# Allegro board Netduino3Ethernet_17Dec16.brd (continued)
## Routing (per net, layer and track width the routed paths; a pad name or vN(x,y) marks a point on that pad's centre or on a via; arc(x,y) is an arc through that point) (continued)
JTMS: length 24.6
  TOP w0.15: U4.72 46.28,28.77 46.27,28.78 46.27,30.1 46,30.38 v1(46,30.9) ; v1(58.25,31.7) 58.25,34.05 v1(55.2,37.1)
  BOTTOM w0.15: v1(55.2,37.1) 53.45,35.35 53.45,34.67 52.13,33.35 48.44,33.35 46.37,31.28 46.37,31.27 v1(46,30.9) ; J8.2 56.55,30.98 56.9,31.33 57.88,31.33 v1(58.25,31.7)
LED: length 16.5
  TOP w0.15: Q1.2 36.23,25.09 37.79,23.52 40.3,23.52 40.43,23.65 41.13,23.65 41.24,23.54 R8.4 41.46,23.11 v1(41.95,23.6)
  TOP w0.18: U4.69 47.78,27.07 48.07,26.78 v1(48.25,26.78)
  L2-GND w0.15: v1(41.95,23.6) 42.87,23.6 43.87,24.6 45.24,24.6 47.42,26.78 v1(48.25,26.78)
LED_GOPORT1: length 10.6
  TOP w0.15: U4.40 v1(57.38,21.08) ; v1(60.26,16.97) 60.65,16.97 60.7,16.93 60.94,16.93 61.42,16.45 63.52,16.45 63.75,16.68 Q10.2
  BOTTOM w0.15: v1(57.38,21.08) 59.3,19.16 59.3,18.8 60.26,17.84 v1(60.26,16.97)
LED_GOPORT2: length 8.7
  TOP w0.15: Q11.5 63.75,23.5 63.45,23.8 63,23.8 61.95,24.85 60.09,24.85 59.66,24.42 59.66,22.36 59.38,22.08 U4.42
LED_GOPORT3: length 9.2
  TOP w0.15: Q11.2 63.75,20.88 63.39,20.52 62.62,20.52 62.43,20.71 v1(61.9,20.71)
  TOP w0.18: U4.45 v1(57.37,23.58)
  BOTTOM w0.15: v1(61.9,20.71) 61.4,21.21 61.4,21.31 60.16,22.55 58.4,22.55 v1(57.37,23.58)
OSC_IN: length 7.5
  TOP w0.2: Y1.2 50.28,8.58 50.5,8.8 50.5,9.75 50.28,9.97 U4.12
  TOP w0.3: Y1.2 48.25,8.45 C18.1
OSC_OUT: length 1.3
  TOP w0.2: U4.13 50.78,11.27 R7.2
OTG_FS_DM: length 1.4
  TOP w0.18: R9.4 47.33,28.68 47.28,28.63 U4.70
OTG_FS_DP: length 1.5
  TOP w0.18: R9.3 46.67,28.68 46.78,28.57 U4.71
PWR_LED: length 19.5
  TOP w0.15: v1(48.15,13.8) 47.78,13.43 U4.7 ; R8.3 41.39,22.46 41.55,22.3 v1(41.55,21.75)
  TOP w0.18: Q1.5 v1(38.89,25.09)
  L2-GND w0.15: v1(41.55,21.75) 43.1,20.2 43.1,18.85 v1(48.15,13.8)
  BOTTOM w0.15: v1(41.55,21.75) 40.7,22.6 40.7,24.24 40.65,24.29 40.65,24.4 39.96,25.09 v1(38.89,25.09)
PWR_ON_GOPORT1: length 26.3
  TOP w0.15: Q6.5 63.75,14.52 62.4,13.17 62.4,13.13 61.34,12.07 60.15,12.07 59.17,13.05 58.25,13.05 55.85,15.45 55.65,15.45 54.31,16.78 53.57,16.78 50.9,19.45 50.9,19.76 50.61,20.06 50.32,20.06 49.53,20.85 45.67,20.85 44.9,20.08 U4.88
PWR_ON_GOPORT2: length 22.1
  TOP w0.15: v1(54.58,23.71) 54.58,24.7 54,25.28 54,26.42 53.98,26.85 53.78,27.05 U4.57
  TOP w0.18: Q6.2 v1(63.75,12.25)
  BOTTOM w0.15: v1(54.58,23.71) 56.7,21.58 58.86,21.58 60.17,20.27 60.17,19.55 62.17,17.55 62.66,17.55 63.02,17.19 63.02,15.52 63.75,14.79 v1(63.75,12.25)
PWR_ON_GOPORT3: length 19.4
  TOP w0.15: Q10.5 v1(63.75,18.2) ; U4.59 52.78,26.82 53.27,26.34 53.27,25.92 52.95,25.6 v1(52.95,24.2)
  BOTTOM w0.15: v1(52.95,24.2) 52.95,24.33 53.53,24.91 54.08,24.91 57.11,21.88 59.98,21.88 60.8,21.06 60.8,20.8 61.1,20.5 61.1,20.38 61.45,20.03 61.45,19.12 62.37,18.2 v1(63.75,18.2)
RD+: length 22.5
  TOP w0.18: D8.3 29.55,42.2 29.21,41.86 29.21,41.45 29.25,41.41 29.25,38.55 28.5,37.8 28.5,36.55 ; 28.5,36.55 T1.11 ; 28.5,36.55 28.76,36.28 31.72,36.28 32.08,36.65 U5.3
  TOP w0.3: T1.11 25.89,36.55 22.8,33.45 22.8,30.29 22.93,30.15 23.68,30.15
RD-: length 23
  TOP w0.18: D8.4 31.6,42.2 32.09,41.71 32.09,41.08 31.89,40.87 31.89,39.84 32.72,39.01 32.72,38.59 32.57,38.44 v1(32.57,38.14) ; v1(34.65,36.5) 34.4,36.25 U5.4 32.15,36.25 31.85,35.95 28.6,35.95 28.43,35.79 28.43,34.19 28.2,33.95 27.32,33.95 T1.9
  TOP w0.3: T1.9 25.5,34.01 23.68,32.17 23.68,31.05
  BOTTOM w0.18: v1(34.65,36.5) 34.21,36.5 v1(32.57,38.14)
RSET_BG: length 1.4
  TOP w0.2: U5.64 34.7,40 R21.1
RX+: length 9.8
  TOP w0.3: T1.6 17.57,36.55 16.75,37.37 16.75,40.35 15.69,41.41 J13.3
RX-: length 5.7
  TOP w0.3: J13.6 16.95,35.92 16.95,34.68 17.62,34.01 T1.8
SCL: length 57.7
  TOP w0.15: v1(41.15,18.73) 41.79,18.08 U4.92
  BOTTOM w0.15: v1(41.15,18.73) 41.58,18.3 43.63,18.3 45.5,20.17 45.5,20.26 46.5,21.26 46.5,22.81 46.11,23.2 43.81,25.5 42.13,25.5 42.08,25.55 41.95,25.55 39.05,28.45 39.05,29.11 37.68,30.48 37.17,30.48 36.7,30.94 36.7,31.82 36.8,31.92 36.8,35.22 37.8,36.22 37.8,37.61 36.15,39.26 36.15,42.81 31.86,47.1 22.5,47.1 J3.10
SDA: length 57.4
  TOP w0.15: U4.93 41.57,17.58 v1(41.15,18)
  BOTTOM w0.15: J3.9 21.34,49.41 23.2,47.55 31.95,47.55 38.1,41.4 38.1,37.32 38.1,37.32 38.1,36.1 37.1,35.1 37.1,31.79 37,31.69 37,31.07 37.29,30.77 37.81,30.77 39.35,29.23 39.35,28.72 42.17,25.9 43.84,25.9 46.24,23.5 46.8,22.94 46.8,19.72 45.08,18 v1(41.15,18)
SPI3_MISO: length 59.7
  TOP w0.15: U4.79 42.32,24.58 42.15,24.75 v1(41.75,24.75)
  TOP w0.18: v1(29.07,11.62) 26.21,11.62 22.13,15.7 16.57,15.7 15.59,16.68 15.35,16.68 14.75,17.29 J9.7 ; R5.4 43.4,8.62 v1(42.93,8.15)
  L2-GND w0.15: v1(41.75,24.75) 40.3,23.3 38.82,23.3 38.2,22.68 38.2,22 38.5,21.7 38.64,21.7 38.94,21.41 38.94,21.26 40.25,19.95 40.25,17.72 40.6,17.37 41.93,17.37 42.4,16.91 42.4,16.9 42.4,14.68 40.4,12.68 40.4,11.09 40.69,10.8 41.93,10.8 43.08,9.66 43.08,9.24 42.93,9.1 v1(42.93,8.15)
  BOTTOM w0.15: v1(29.07,11.62) 30.45,10.25 38,10.25 40.1,8.15 v1(42.93,8.15)
SPI3_MOSI: length 28.8
  TOP w0.15: v1(39.87,24.02) 40.46,24.02 40.54,24.1 42.16,24.1 42.18,24.08 U4.80
  TOP w0.18: v1(18.76,17.02) 19.15,17.41 J9.3
  BOTTOM w0.15: v1(39.87,24.02) 39.56,23.71 38.81,23.71 36.35,21.25 31.65,21.25 29.95,19.55 28.75,19.55 27.15,17.95 26.96,17.95 26.91,17.9 25.08,17.9 24.73,18.25 19.93,18.25 18.76,17.08 v1(18.76,17.02)
SPI3_SCK: length 34.9
  TOP w0.15: U4.78 42.13,25.08 41.96,25.25 40.23,25.25 39.21,24.23 v1(39.18,24.23)
  TOP w0.18: J9.5 16.95,17.1 17.8,16.25 v1(19.07,16.25)
  BOTTOM w0.15: v1(19.07,16.25) 19.26,16.44 19.26,17.16 20.05,17.95 24.61,17.95 24.96,17.6 27.03,17.6 27.08,17.65 27.55,17.65 29.11,19.21 30.04,19.21 31.77,20.95 36.55,20.95 38.96,23.36 39.92,23.36 40.37,23.81 40.37,24.15 40.35,24.17 40.35,24.25 40,24.6 39.55,24.6 v1(39.18,24.23)
SPI4_MISO: length 61.7
  TOP w0.15: 74.3,25.4 74.3,23.16 74.9,22.56 74.9,21.49 74.21,20.8 72.7,20.8 ; 74.3,25.4 73.8,25.9 73.8,30.73 73.29,31.23 73.29,32.27 76.55,35.52 76.55,36.9 74.25,39.2 74.25,41.7 74.5,41.95 75.92,41.95 J12.8 ; 74.3,25.4 J11.8 ; 72.7,20.8 71.5,22 71.5,22.16 69.96,23.7 64.2,23.7 63.8,24.1 63.12,24.1 62.07,25.15 59.97,25.15 59.36,24.54 59.36,23.24 59.2,23.08 U4.44 ; 72.7,20.8 72.53,20.63 72.53,16.32 74.07,14.78 74.07,14.22 74.05,14.2 74.05,11.66 74.35,11.36 74.35,10.58 73.78,10.01 73.78,9.38 74.33,8.82 J10.8
SPI4_MOSI: length 74.2
  TOP w0.15: J12.7 69.33,41.98 68.65,41.3 68.65,32.45 v1(70.25,30.85) ; 69.75,9.3 70.23,8.82 J10.7 ; 69.75,9.3 69.75,16.17 71.75,18.17 71.75,18.61 71,19.36 v1(71,21.95) ; 69.75,9.3 69,9.3 66.91,11.39 59.9,11.39 58.9,12.39 58.11,12.39 58.08,12.42 58.06,12.42 58.03,12.45 58,12.45 55.63,14.82 55.35,14.82 54.01,16.16 52.27,16.16 50.13,18.3 49.22,18.3 47.92,17 47.92,14.78 46.78,13.63 U4.5
  TOP w0.18: v1(70.39,24.59) 70.39,25.03 70.76,25.4 J11.7
  BOTTOM w0.15: v1(70.25,30.85) 70.25,27.65 70.9,27 70.9,25.1 v1(70.39,24.59)
  BOTTOM w0.18: v1(70.39,24.59) 71,23.99 v1(71,21.95)
SPI4_SCK: length 76.7
  TOP w0.15: U4.1 44.78,15.09 48.29,18.6 50.3,18.6 52.41,16.48 54.15,16.48 55.51,15.12 55.76,15.12 58.13,12.75 58.15,12.75 58.18,12.72 59.04,12.72 60.04,11.72 67.98,11.72 v1(69,10.7) ; J11.9 72.07,24.11 73.57,24.11 ; J12.9 72.05,40.06 69.7,37.72 69.7,34.4 73.5,30.6 73.5,25.78 73.57,25.7 73.57,24.11 ; 73.57,24.11 73.57,23.18 v1(74.4,22.35) ; v1(73.57,14.55) 73.57,11.43 v1(73.85,11.15) 73.85,10.51 73.47,10.13 73.47,9.25 73.65,9.08 73.65,7.7 73.5,7.55 J10.9
  BOTTOM w0.15: v1(73.85,11.15) 70.9,11.15 70.45,10.7 v1(69,10.7)
  BOTTOM w0.18: v1(74.4,22.35) 74.4,21.81 74.56,21.64 74.56,15.54 v1(73.57,14.55)
SWITCH1: length 103.1
  TOP w0.15: v1(59.62,17.32) 60.15,17.84 R12.1 ; SW1.4 12.2,47.78 13.13,46.85 21.82,46.85 22.95,45.73 v1(22.95,45.2) ; v1(41.87,18.8) 42.09,18.58 U4.91 43.8,18.58 43.95,18.43 43.95,17.23 43.8,17.08 U4.94 ; U4.58 53.28,27.13 53.57,26.84 53.57,25.28 53.74,25.11 v1(53.74,24.41)
  L2-GND w0.15: v1(41.87,18.8) 42.24,19.17 42.24,20.35 41.05,21.54 41.05,21.96 41.34,22.25 41.76,22.25 45.06,18.95 51.35,18.95 52.1,18.2 55.25,18.2 55.47,17.98 56.13,17.98 56.74,18.59 58.35,18.59 v1(59.62,17.32)
  BOTTOM w0.15: v1(59.62,17.32) 57.86,19.07 57.86,19.71 53.74,23.84 v1(53.74,24.41) ; v1(22.95,45.2) 23.48,45.2 23.62,45.35 28.75,45.35 29.35,44.75 29.35,44.55 30.12,43.78 31.83,43.78 32.25,43.36 32.25,42.94 31.07,41.77 31.07,41.61 31.04,41.57 31.04,41.16 31.07,41.12 31.07,40.1 31.82,39.35 32.5,39.35 34.25,37.61 34.25,37.29 34.54,37 34.86,37 35.85,36.01 35.85,35.99 36.14,35.7 36.16,35.7 36.5,35.36 36.5,32.04 36.4,31.94 36.4,31.07 36.4,30.82 37.04,30.18 37.56,30.18 38.75,28.98 38.75,28.28 41.78,25.25 41.96,25.25 42.11,25.1 43.79,25.1 46.2,22.69 46.2,21.38 45.2,20.38 45.2,20.29 43.71,18.8 v1(41.87,18.8)
TD+: length 31.6
  TOP w0.18: T1.16 28.25,42.9 28.5,42.65 v1(28.85,42.65) 28.85,42.95 29.1,43.2 D8.1 ; U5.6 32.5,35.45 32.35,35.6 v1(32.23,35.6)
  TOP w0.3: T1.16 25.95,42.9 21.75,38.7 21.75,29.48 22.77,28.45 23.68,28.45
  BOTTOM w0.15: v1(32.23,35.6) 32.23,37.78 31.68,38.33 31.38,38.33 31.05,38.66 31.05,38.71 29.23,40.53 29.23,42.27 v1(28.85,42.65)
TD-: length 32.4
  TOP w0.18: v1(31.75,43.15) 31.7,43.2 D8.6 ; v1(31.88,34.97) 32.42,34.97 32.51,35.05 U5.7 ; T1.14 28.31,40.35 v1(28.72,40.76)
  TOP w0.3: T1.14 26.11,40.35 22.2,36.45 22.2,29.93 22.77,29.35 23.68,29.35
  BOTTOM w0.15: v1(31.88,34.97) 31.73,35.12 31.73,35.83 31.85,35.95 31.85,37.73 31.56,38.02 31.26,38.02 30.75,38.53 30.43,38.53 28.93,40.03 28.93,40.55 v1(28.72,40.76)
  BOTTOM w0.18: v1(28.72,40.76) 28.34,41.15 28.34,42.86 28.69,43.21 30.09,43.21 30.09,43.22 30.51,43.22 30.51,43.21 31.15,43.21 31.21,43.15 v1(31.75,43.15)
TX+: length 6.4
  TOP w0.3: J13.1 16.05,43.95 17.11,42.9 T1.1
TX-: length 4.4
  TOP w0.3: J13.2 17.59,40.35 T1.3
USART3_RX_GOPORT1: length 30.6
  TOP w0.15: v1(70.35,9.4) 70.35,9.93 70.52,10.09 J10.5 ; v1(55.4,24.3) 54.3,25.4 54.3,26.96 54.28,26.98 U4.56
  BOTTOM w0.15: v1(70.35,9.4) 69.66,10.1 68.89,10.1 68.5,10.49 68.5,10.75 65.53,13.72 65.45,13.72 64.53,14.65 64.53,14.87 63.9,15.49 63.9,17.1 64.25,17.45 64.25,18.41 63.96,18.7 62.29,18.7 61.77,19.22 61.77,20.13 61.4,20.5 61.4,20.63 61.1,20.93 61.1,21.18 60.1,22.18 57.52,22.18 v1(55.4,24.3)
USART3_TX_GOPORT1: length 44.1
  TOP w0.15: U4.55 54.78,28.98 v1(54.85,29.05) ; v1(54.2,30.85) 53.83,31.22 53.83,31.27 53.65,31.45 R1.7 ; v1(74.05,21.35) 72.93,21.35 67.85,26.43 67.85,30.75 66.05,32.55 v1(64.2,32.55) ; J10.4 75.67,11.64 74.49,11.64 74.35,11.78 74.35,14.05 74.37,14.07 74.37,15.53 73.9,16 v1(73.9,17.8)
  L2-GND w0.15: v1(64.2,32.55) 61.75,32.55 58.95,29.75 57.7,29.75 57,29.05 v1(54.85,29.05)
  BOTTOM w0.15: v1(73.9,17.8) 73.9,21.2 v1(74.05,21.35) ; v1(54.85,29.05) 54.85,30.2 v1(54.2,30.85)
USART7_RX_GOPORT2: length 23.7
  TOP w0.15: J11.5 70.59,26.67 70.25,26.32 v1(70.25,25.61) ; U4.38 v1(55.07,20.08)
  L2-GND w0.15: v1(55.07,20.08) 58.04,23.05 64.31,23.05 64.88,23.62 65.53,23.62 65.63,23.53 68.23,23.53 69.4,24.7 69.4,24.76 v1(70.25,25.61)
USART7_TX_GOPORT2: length 52.5
  TOP w0.15: U4.39 54.09,20.58 54.06,20.55 53.64,20.55 53.35,20.84 53.35,20.97 51.91,22.42 51.91,23.89 50.59,25.21 49.72,25.21 49.43,25.5 49.43,25.92 49.72,26.21 50.65,26.21 51.26,25.6 v1(52,25.6) ; R1.6 53.6,30.95 53.7,30.85 53.7,30.64 53.88,30.46 53.88,30.04 v1(53.92,30.01) ; v1(73.79,31.89) 73.79,31.16 74.2,30.75 74.2,28.24 74.5,27.94 J11.4 ; v1(58.93,32.32) 59.57,32.32 60.6,33.35 66.55,33.35 69.55,30.35 70.53,30.35 71.05,30.87 71.05,31.39 v1(71.53,31.87)
  BOTTOM w0.15: v1(58.93,32.32) 57.47,32.32 56.35,31.2 54.97,31.2 54.82,31.35 53.99,31.35 53.7,31.06 53.7,30.22 v1(53.92,30.01) 53.92,27.98 52.27,26.34 52.27,25.84 52.03,25.6 v1(52,25.6) ; v1(71.53,31.87) 72.05,31.87 72.08,31.89 v1(73.79,31.89)
USART8_RX_GOPORT3: length 45.6
  TOP w0.15: v1(49.15,20.05) 48.5,20.05 44.03,15.58 U4.97 ; v1(67.5,43.45) 70.4,43.45 70.6,43.25 J12.5
  BOTTOM w0.15: v1(67.5,43.45) 62.75,38.7 59.45,38.7 59.27,38.52 54.98,34.23 54.98,33.24 52.76,31.02 52.76,29.96 52.74,29.95 52.74,29.53 52.76,29.51 52.76,27.68 51.67,26.58 51.67,26.53 51.03,25.9 51.03,25.5 51.03,25.26 49.15,23.37 v1(49.15,20.05)
USART8_TX_GOPORT3: length 57.2
  TOP w0.15: v1(73.6,47.85) 74.25,47.2 74.25,44.77 74.5,44.52 J12.4 ; U4.98 44.32,15.08 48.77,19.52 v1(49.67,19.52) ; v1(53.24,29.74) 53.24,30.26 R1.5
  BOTTOM w0.15: v1(49.67,19.52) 49.67,20.23 49.55,20.36 49.55,23.35 51.33,25.13 51.33,25.77 51.97,26.41 51.97,26.46 53.24,27.74 v1(53.24,29.74) 53.24,31.07 55.28,33.11 55.28,34.11 59.47,38.3 63.06,38.3 69.7,44.94 69.7,47.15 71.1,48.55 72.9,48.55 v1(73.6,47.85)
USB5V: length 4.3
  TOP w0.3: 7.05,23.52 7.05,24.65 F1.1
  TOP w0.4: J5.1 5.87,24.12 6.55,24.8 F1.1
USB5V_F: length 65
  TOP w0.15: Q3.3 5,30.62 5.7,31.32 6.7,31.32 7.12,31.75 8.9,31.75 9.12,31.52 9.12,29.62 9.6,29.15 10.55,29.15 10.75,28.95 11.52,28.95 12.18,28.3 12.18,28.29 13.31,27.15 19.11,27.15 19.22,27.04 27.39,27.04 28.2,27.85 35.74,27.85 36.44,28.55 36.86,28.55 37.06,28.35 37.3,28.35 37.48,28.17 40,28.17 41.12,29.3 41.12,32.42 v1(40.27,33.27)
  TOP w0.18: U4.68 v1(48.28,28.97)
  TOP w0.8: Q3.3 5.85,28.85 F1.2
  BOTTOM w0.15: v1(48.28,28.97) 47.12,28.97 42.2,33.89 42.2,34.64 41.11,35.73 40.33,35.73 39.3,34.71 39.3,34.25 v1(40.27,33.27)
USB_D+: length 49.1
  TOP w0.18: 6.55,22.7 5.24,22.7 5.12,22.82 J5.3 ; 6.55,22.7 D4.1 ; 6.55,22.7 8.3,22.7 8.5,22.5 8.5,22.15 8.6,22.05 8.85,22.05 8.98,22.18 8.98,22.57 9.1,22.7 9.5,22.7 10.45,23.65 10.45,24.21 12.25,26 12.72,26.47 18.88,26.47 18.95,26.39 27.69,26.39 28.49,27.19 40.39,27.19 42.2,29 42.2,29.48 44.13,31.42 46.35,31.42 46.67,31.09 R9.2
USB_D-: length 49
  TOP w0.18: 6.55,23.04 5.55,23.04 5.12,23.47 J5.2 ; 6.55,23.04 9.34,23.04 10.12,23.82 10.12,24.07 10.12,24.34 12.11,26.34 12.11,26.34 12.41,26.64 12.58,26.8 19.01,26.8 19.09,26.72 27.56,26.72 28.35,27.52 40.25,27.52 41.87,29.14 41.87,29.62 43.76,31.51 43.99,31.75 46.67,31.75 47.33,31.09 R9.1 ; 6.55,23.04 6.55,23.52
VCAP_1: length 2.5
  TOP w0.25: C17.1 59.94,25.7 59.82,25.58 U4.49
VCAP_2: length 2.1
  TOP w0.3: C16.1 45.5,29.15 45.78,28.87 U4.73
XTALIN: length 8.5
  TOP w0.2: U5.61 35.9,39.45 36.32,39.87 36.32,40.32 R16.1 36.5,40.55 36.35,40.7 36.35,41.35 36.6,41.6 36.6,42.7 37.3,43.4 Y2.2 39.25,44.1 C37.1
XTALOUT: length 8.6
  TOP w0.2: U5.62 35.5,39.6 35.75,39.85 35.75,40.35 R16.2 35.6,40.55 35.75,40.7 35.75,41.25 36.25,41.75 36.25,42.7 35.55,43.4 Y2.1 33.55,44.1 C38.1
N332853: length 10.3
  TOP w0.15: R5.8 44.4,10.8 44.05,11.15 44.05,11.35 43.2,12.2 41.91,12.2 41.85,12.14 39.06,12.14 38.52,11.61 38.52,11.19 38.97,10.75 39,10.75 ; Q2.3 39.15,10.1 39,10.25 39,10.75 ; 39,10.75 Q2.2
N332873: length 2.9
  TOP w0.6: L1.1 38.33,15.65 U1.5
N332891: length 23.4
  TOP w0.15: R1.1 51.9,33.19 50.95,34.14 50.95,35.02 51.85,35.92 51.85,36.58 51.45,36.98 v1(51.45,41.65) ; D2.C 61.76,42.61 59.65,40.5 55.55,40.5 v1(54.65,41.4)
  BOTTOM w0.15: v1(54.65,41.4) 53.15,41.4 52.9,41.65 v1(51.45,41.65)
N333149: length 24.5
  TOP w0.15: v1(36.65,28.05) 37.17,28.05 37.35,27.87 40.12,27.87 41.55,29.3 41.55,29.85 v1(44.25,32.55) ; Q1.6 37.69,26.19 37.58,26.3 v1(36.8,26.3) ; v1(52.1,34.35) 52.1,33.7 53.1,32.7 R1.8
  BOTTOM w0.15: v1(36.65,28.05) 36.65,27.25 36.8,27.1 v1(36.8,26.3) ; v1(44.25,32.55) 45.8,32.55 47,33.75 51.5,33.75 v1(52.1,34.35)
N333173: length 2.4
  TOP w0.2: R3.1 8.91,18.33 9.79,19.2 9.8,19.2 D1.C
N333175: length 35.9
  TOP w0.15: v1(24.4,17.45) 25.85,18.9 27.6,18.9 27.95,18.55 29.76,18.55 29.76,18.55 31.76,18.55 32.4,19.18 32.4,21.3 35,23.9 35.64,23.9 35.79,24.05 Q1.3 ; v1(11.55,17.98) 10.89,17.98 9.64,16.73 R3.2
  BOTTOM w0.15: v1(11.55,17.98) 11.92,18.35 13.25,18.35 14.45,17.15 14.45,15.59 14.74,15.3 18.83,15.3 19.57,16.05 19.57,16.36 19.56,16.37 19.56,17.03 20.03,17.5 20.69,17.5 20.74,17.45 v1(24.4,17.45)
N333299: length 6.1
  TOP w0.2: Y1.1 51.17,8.58 51,8.75 51,9.75 51.75,10.5 51.75,11 R7.1
  TOP w0.3: Y1.1 52.81,8.45 C19.1
N333445: length 12.9
  TOP w0.18: J9.1 21.35,17.29 26.57,12.06 28.56,12.06 29.15,12.65 29.15,13.59 28.99,13.75 R11.6
N333449: length 23.4
  TOP w0.18: R11.7 29.12,14.25 29.59,13.78 29.59,11.41 29.29,11.11 26.26,11.11 22,15.37 16.38,15.37 15.39,16.35 14.45,16.35 13.65,17.15 J9.8
N337920: length 7.7
  TOP w0.15: Q10.6 62.65,18.95 62.4,19.2 v1(62.4,19.3) ; v1(60.2,24.25) 60.15,24.2 R15.8
  BOTTOM w0.15: v1(60.2,24.25) 60.2,24.25 60.2,23.11 62.19,21.12 62.2,21.12 62.4,20.92 62.4,19.3 v1(62.4,19.3)
N337928: length 32.1
  TOP w0.15: v1(59.58,20.15) 59.58,20.91 60.15,21.48 R15.1
  TOP w0.18: v1(71.45,2.55) D5.C
  BOTTOM w0.15: v1(59.58,20.15) 59.67,20.06 59.67,19.03 61.25,17.45 61.25,16.7 61.4,16.55 61.4,11.59 60.95,11.14 60.95,4.9 61.5,4.35 62.35,4.35 62.85,3.85 64.15,3.85 66,2 70.9,2 v1(71.45,2.55)
N337930: length 6.3
  TOP w0.15: R15.7 60.7,23.3 60.7,24.13 v1(60.92,24.35) ; Q11.3 64.35,21.1 64.35,21.6 v1(63.85,22.1)
  BOTTOM w0.15: v1(63.85,22.1) 63.43,22.52 62.75,22.52 v1(60.92,24.35)
N337938: length 16.3
  TOP w0.15: v1(71.25,18.4) 70.45,19.2 69.1,19.2 67.93,20.38 64.97,20.38 64.82,20.52 63.82,20.52 63.5,20.21 61.65,20.21 60.7,21.16 R15.2 ; v1(73.1,17.85) 73.1,19.05 D6.C
  BOTTOM w0.15: v1(73.1,17.85) 72.55,18.4 v1(71.25,18.4)
N337940: length 3
  TOP w0.15: Q11.6 63.1,23.05 62.72,23.43 62.72,23.65 62.45,23.93 61.35,23.93 61.2,23.77 R15.6
N337948: length 24.3
  TOP w0.15: v1(62.4,21.62) 62.03,21.25 61.42,21.25 61.2,21.48 R15.3
  TOP w0.18: v1(70.2,35.4) 72.14,35.4 72.49,35.75 D7.C
  BOTTOM w0.15: v1(70.2,35.4) 67.45,32.65 67.45,24.85 66.45,23.85 65.12,23.85 64.35,23.08 64.35,21.89 63.76,21.3 62.72,21.3 v1(62.4,21.62)
N337960: length 36.7
  TOP w0.15: v1(29.25,16.93) 28.9,16.58 Q4.3 ; v1(50.5,32.65) 51.15,32 51.15,31.57 51.27,31.45 R1.2
  L2-GND w0.15: v1(29.25,16.93) 30.78,16.93 34.05,20.2 34.05,29.18 34.49,29.62 35.67,29.62 35.97,29.93 40.92,29.93 44.04,33.05 46.2,33.05 46.45,33.3 48.45,33.3 49.1,32.65 v1(50.5,32.65)
N337994: length 2.2
  TOP w0.15: Q8.6 50.7,31.8 50.85,31.65 50.85,31.38 51.27,30.95 R1.3
N338028: length 4.6
  TOP w0.15: Q8.3 48.78,30.5 49.93,29.35 50.4,29.35 50.69,29.64 50.69,29.81 51.27,30.4 R1.4
N338320: length 11.8
  TOP w0.18: R19.2 31.96,24.94 31.85,25.05 v1(31.7,25.05) ; U5.12 32.65,33.05 32.47,32.87 v1(32,32.87)
  BOTTOM w0.15: v1(31.7,25.05) 31.28,25.47 31.28,26.05 31.91,26.68 31.91,29.54 32.88,30.51 32.88,32.52 32.52,32.87 v1(32,32.87)
N338324: length 10
  TOP w0.18: v1(31.78,25.77) 32.07,25.49 R19.1 ; U5.13 v1(34.52,32.65)
  BOTTOM w0.15: v1(34.52,32.65) 33.53,31.66 33.53,30.74 32.25,29.46 32.25,26.24 v1(31.78,25.77)
N338328: length 25.8
  TOP w0.15: v1(32.4,23.1) 32.1,22.8 32.1,19.31 31.64,18.84 29.89,18.84 29.88,18.85 29.55,18.85 29.4,19 R13.2
  TOP w0.18: U5.57 37.5,37.99 37.96,37.53 37.96,34.21 v1(36,32.25)
  BOTTOM w0.15: v1(36,32.25) 35.54,31.79 34.91,31.79 34.6,31.48 34.6,29.85 33.55,28.8 33.55,26.39 32.4,25.24 v1(32.4,23.1)
N338332: length 10.3
  TOP w0.15: R19.6 34.85,24.44 35.14,24.73 35.14,25.14 34.85,25.44 34.84,25.44 33.77,26.5 v1(32.95,26.5)
  TOP w0.18: U5.16 33.45,30.8 v1(34,30.25)
  BOTTOM w0.15: v1(34,30.25) 33.55,29.8 33.55,29.34 32.95,28.74 v1(32.95,26.5)
N338402: length 16.9
  TOP w0.18: R14.5 38.14,21.5 v1(38.44,21.2) ; U5.21 v1(36.3,29.12)
  BOTTOM w0.15: v1(38.44,21.2) 39.24,22 40.59,22 41.34,21.25 41.76,21.25 42.05,21.54 42.05,22.55 41.04,23.56 41.04,24.33 40.95,24.42 40.95,24.75 37.15,28.55 36.88,28.55 v1(36.3,29.12)
N338408: length 14.2
  TOP w0.15: v1(31.35,23.55) 31.75,23.55 32.09,23.89 R19.4
  TOP w0.18: U5.20 v1(35.9,31.27)
  BOTTOM w0.15: v1(35.9,31.27) 35.9,30.75 35.8,30.65 35.8,29.4 33.9,27.5 33.9,26.3 32.9,25.3 32.9,22.89 32.61,22.6 32.19,22.6 31.9,22.89 31.9,23 v1(31.35,23.55)
N338436: length 3.6
  TOP w0.3: R17.6 27,29.35 C51.1 27.14,28.92 26.68,28.45 R17.5
N338444: length 3.8
  TOP w0.3: R17.8 26.75,31.05 27.14,30.65 C39.1 27.11,30.07 26.48,30.07 26.4,30.15 R17.7
N338526: length 11.6
  TOP w0.3: R18.4 12.46,33.8 11.54,34.72 11.54,37.67 J13.5 14,38.87 J13.4
N338532: length 8.5
  TOP w0.3: R18.3 13.35,33.85 12.73,34.47 J13.7 14,36.33 J13.8
N338540: length 17.3
  TOP w0.3: T1.2 20.02,41.62 20.85,40.8 20.85,33.3 20.1,32.55 15.35,32.55 15.04,32.25 R18.1
N338544: length 10.5
  TOP w0.3: T1.7 19.89,35.27 20.15,35.02 20.15,33.5 19.75,33.1 15.18,33.1 14.15,32.08 R18.2
N338558: length 8.2
  TOP w0.3: C40.1 15.2,28.1 15.04,28.25 ; 15.04,28.25 14.15,28.25 ; 15.04,28.25 R18.8 ; 14.15,28.25 R18.7 ; 14.15,28.25 13.35,28.25 ; 13.35,28.25 R18.6 ; 13.35,28.25 12.79,28.25 12.55,28.5 12.55,29.13 R18.5
N3392501: length 18.5
  TOP w0.18: R22.4 12.59,45.67 12.42,45.51 8.95,45.51 6.8,47.65 2.98,47.65 2.4,48.23 D9.1
N3395001: length 17.9
  TOP w0.18: R22.3 12.77,46.33 12.28,45.84 10.7,45.84 6.71,49.82 4.54,49.82 3.77,49.05 D9.2

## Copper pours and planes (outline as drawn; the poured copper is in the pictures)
+3.3V on TOP: 35.1,14 35.1,11.25 37.7,11.25 38,11.55 38,11.85 39,12.85 40.05,12.85 40.05,13.9 36.6,13.9 36.5,14
+3.3V on L3-PWR: outline of 91 points within 9.5,8.5 67.5,48.25
+5.0V on TOP: 29.85,17.75 29.85,15.4 30.2,15.4 30.2,14.6 31.75,14.6 31.75,15.4 33.5,15.4 33.5,17.75
+5.0V on TOP: 3.45,27.5 1.35,27.5 1.35,30.1 2.25,30.1 2.25,28.3 3.45,28.3
+5.0V on TOP: 17.95,26.2 17.95,19.2 28.1,19.2 28.1,21.2 30.8,21.2 30.8,22.9 28.1,22.9 28.1,26.2
+5.0V on BOTTOM: 0.5,0.5 0.5,35.75 8.75,35.75 9.81,36.19 10.25,37.25 10.25,41.75 9.81,42.81 8.75,43.25 0.5,43.25 0.5,52.75 15.25,52.75 15.25,50.75 18.75,50.75 22.5,47 23.5,47 23.5,45.25 28.75,45.25 28.75,38.25 28.25,37.75 28.25,34.25 28.75,33.75 28.75,32 28.25,31.5 28.25,26 28.75,25.5 28.75,0.5 ; 2 cut-outs
+5.0V on L2-GND: 17.75,19.25 17.75,26.5 28.25,26.5 28.25,19.25
+5.0V on L3-PWR: 0.5,52.75 0.5,43.25 8.75,43.25 9.81,42.81 10.25,41.75 10.25,37.25 9.81,36.19 8.75,35.75 0.5,35.75 0.5,0.5 76.25,0.5 77.5,1.75 77.5,51.5 76.25,52.75
GND on TOP: 0.5,0.5 0.5,35.75 8.75,35.75 9.81,36.19 10.25,37.25 10.25,41.75 9.81,42.81 8.75,43.25 0.5,43.25 0.5,52.75 76.25,52.75 77.5,51.5 77.5,1.75 76.25,0.5 ; 68 cut-outs
GND on TOP: 33.8,15.75 34.8,15.75 34.8,13.4 34.25,12.85 34.25,11.45 30.25,11.45 30.25,12.5 32.1,12.5 32.1,13.1 32.15,13.15 33.8,13.15 33.8,14.45 32.4,14.45 32.4,14.9 32.45,14.95 33.8,14.95
GND on TOP: 5.75,21.7 5.75,19.2 6.75,19.2 6.75,21.7
GND on BOTTOM: 0.5,52.75 0.5,43.25 8.75,43.25 9.81,42.81 10.25,41.75 10.25,37.25 9.81,36.19 8.75,35.75 0.5,35.75 0.5,0.5 76.25,0.5 77.5,1.75 77.5,51.5 76.25,52.75 ; 20 cut-outs
GND on L2-GND: 0.5,52.75 0.5,43.25 8.75,43.25 9.81,42.81 10.25,41.75 10.25,37.25 9.81,36.19 8.75,35.75 0.5,35.75 0.5,0.5 76.25,0.5 77.5,1.75 77.5,51.5 76.25,52.75 ; 11 cut-outs
VCC3A3 on L3-PWR: 32.25,46.5 32.5,46.25 32.5,45 31.75,44.25 31.75,43 32.75,42 32.75,39.75 31.5,39.75 30.75,39 30.75,37.25 28,37.25 26.25,35.5 26.25,35 25.75,35 25.5,35.25 25.5,45.25 26.75,46.5
VCC18 on L3-PWR: 43.75,34.25 43.75,34.75 43.5,35 43.25,35 41.5,36.75 41.5,39.5 40.25,40.75 39.63,40.75 38.13,39.25 37.25,39.25 37,39.5 31.5,39.5 31,39 31,37.25 31.5,37.25 31.75,37 31.75,36.5 31.5,36.25 30.75,36.25 28.75,34.25 28.75,33.25 30.25,33.25 30.5,33.5 30.5,33.75 31.5,34.75 32.5,34.75 35.75,38 36,38 36.5,37.5 36.5,36.25 35.25,35 35.25,34.75 37.25,32.75 37.25,30 39.5,30
VCC18A on L3-PWR: 31.5,34.5 30.75,33.75 30.75,33.5 30.25,33 28.75,33 28.75,31.5 28.5,31.25 28.5,30.75 28.75,30.5 29.25,30.5 32,33.25 33.25,33.25 36.25,36.25 36.25,37.5 36,37.75 35.75,37.75 32.5,34.5
VCCIO on L3-PWR: 37,41.5 37,39.75 37.25,39.5 38.08,39.5 38.1,39.55 39.3,40.75 40.25,40.75 41.75,39.25 41.75,36.75 43.25,35.25 43.5,35.25 44,34.75 44,34.25 39.5,29.75 37.25,29.75 37.25,29.25 38.42,28.08 41.08,28.08 46,33 46,38.25 42,42.25 37.75,42.25
CHASSIS_USB on BOTTOM: 0.5,27.25 0.5,18.5 5,18.5 5,22 6.75,22 7,21.75 7,21 8,21 8,21.75 5.5,24.25 5,24.25 5,27.25

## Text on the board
Ref Des/Silkscreen Top: 7.5-12V | ACT | MicroSD | REV.A | PWR | Power | Digital I/O | Analog In | LED | SC | SD | GND | 13 | IOREF | 12 | /RESET | 11 | 3V3 | 10 | 5V | 9 | 8 | 7 | VIN | 6 | 5 | 0 | 4 | 1 | 3 | 2
User.6: FIGURE | SIZE | 0.25 | 0.3302 | 0.5 | 0.8 | 0.89 | 1.0 | 1.8 | 2.4 | 3.2 | 3.25 | 1.0x0.75 | 1.3x0.75 | DRILL CHART: TOP to BOTTOM | ALL UNITS ARE IN MILLIMETERS | TOLERANCE | +0.08/-0.08 | +0.1/-0.0 | +0.076/-0.076 | PLATED | NON-PLATED | QTY | 344 | 65 | 21 | 32 | 8 | 6 | 3 | 1 | 2
